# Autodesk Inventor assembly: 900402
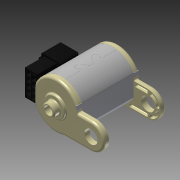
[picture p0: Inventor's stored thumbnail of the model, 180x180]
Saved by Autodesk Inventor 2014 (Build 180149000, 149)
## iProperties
Created: 2007-10
Part Number: 900402
Document SubType Name: Assembly
Designer: TH
Mass: 85.0345 g
Surface Area: 363.511 cm^2
Volume: 33.1568 cm^3
Density: 2.56462 g/cm^3
Description: 1300 SERVO MOTOR
Component Category: Electrical
Author: TH
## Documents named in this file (5)
- C:\Users\iTools\Desktop\tutorial files\Automotive\9000\900402.iam
- C:\Users\iTools\Desktop\tutorial files\Automotive\9000\900985.ipt
- C:\Users\iTools\Desktop\tutorial files\Automotive\9000\901230.ipt
- C:\Users\iTools\Desktop\tutorial files\Automotive\9000\900569.ipt
- C:\Users\iTools\Desktop\tutorial files\Automotive\9000\901253.ipt
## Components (4 placed, 4 different names)
1. 900985:1 — Mate:6, Mate:8
2. 901230:1
3. 900569:1 — Mate:7
4. 901253:1 — Mate:6, Mate:7, Mate:8
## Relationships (3: Mate 3)
- Mate:6: 900985:1 ↔ 901253:1
- Mate:7: 900569:1 ↔ 901253:1
- Mate:8: 900985:1 ↔ 901253:1
